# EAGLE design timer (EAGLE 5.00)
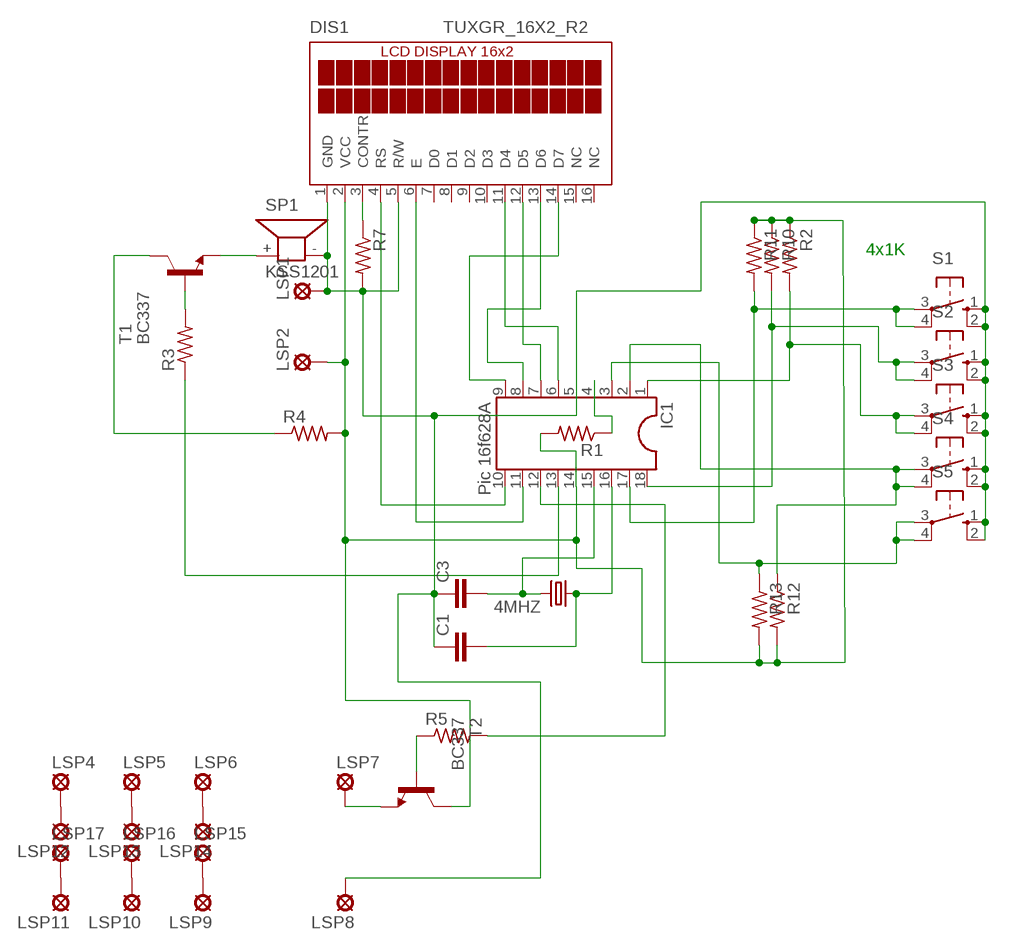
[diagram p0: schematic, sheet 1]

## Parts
4MHZ  CRYSTALHC18U-V  [HC18U-V]
C1  C2,5-3  [C2.5-3]
C3  C2,5-3  [C2.5-3]
DIS1  TUXGR_16X2_R2  [TUXGR_16X2_R2]
IC1  Pic 16f628A  DIL18  [DIL18]
LSP1  SE14  [SE14]
LSP2  SE14  [SE14]
LSP4  LSP10  [LSP10]
LSP5  LSP10  [LSP10]
LSP6  LSP10  [LSP10]
LSP7  LSP10  [LSP10]
LSP8  LSP10  [LSP10]
LSP9  LSP10  [LSP10]
LSP10  LSP10  [LSP10]
LSP11  LSP10  [LSP10]
LSP12  LSP10  [LSP10]
LSP13  LSP10  [LSP10]
LSP14  LSP10  [LSP10]
LSP15  LSP10  [LSP10]
LSP16  LSP10  [LSP10]
LSP17  LSP10  [LSP10]
R1  R-US_0204/7  [0204/7]
R2  R-US_0204/7  [0204/7]
R3  R-US_0204/7  [0204/7]
R4  R-US_0204/7  [0204/7]
R5  R-US_0204/7  [0204/7]
R7  R-US_0204/7  [0204/7]
R10  R-US_0204/7  [0204/7]
R11  R-US_0204/7  [0204/7]
R12  R-US_0204/7  [0204/7]
R13  R-US_0204/7  [0204/7]
S1  10-XX  [B3F-10XX]
S2  10-XX  [B3F-10XX]
S3  10-XX  [B3F-10XX]
S4  10-XX  [B3F-10XX]
S5  10-XX  [B3F-10XX]
SP1  KSS1201  [KSS1201]
T1  BC337  [TO92]
T2  BC337  [TO92]

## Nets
N$1: DIS1.3(CONTR) R7.1
N$2: 4MHZ.2 C3.2 IC1.15
N$3: DIS1.12(D5) IC1.7
N$4: IC1.12 R5.2
N$5: C1.1 C3.1 DIS1.1(GND) DIS1.5(R/W) IC1.5 LSP1.MP LSP8.MP R7.2 S1.1(S) S1.2(S1) S2.1(S) S2.2(S1) S3.1(S) S3.2(S1) S4.1(S) S4.2(S1) S5.1(S) S5.2(S1) SP1.-
N$6: IC1.4 R1.1
N$7: IC1.13 R3.1
N$8: DIS1.11(D4) IC1.6
N$9: DIS1.2(VCC) IC1.14 LSP2.MP R1.2 R2.1 R4.2 R10.1 R11.1 R12.2 R13.2 T2.3(C)
N$10: DIS1.4(RS) IC1.10
N$11: DIS1.6(E) IC1.11
N$12: DIS1.14(D7) IC1.9
N$13: SP1.+ T1.1(E)
N$14: IC1.3 R13.1 S5.3(P) S5.4(P1)
N$15: R4.1 T1.3(C)
N$16: IC1.17 R11.2 S1.3(P) S1.4(P1)
N$17: R3.2 T1.2(B)
N$18: 4MHZ.1 C1.2 IC1.16
N$19: LSP4.MP LSP12.MP
N$20: IC1.18 R10.2 S2.3(P) S2.4(P1)
N$21: IC1.1 R2.2 S3.3(P) S3.4(P1)
N$22: LSP5.MP LSP13.MP
N$23: LSP6.MP LSP14.MP
N$24: IC1.2 R12.1 S4.3(P) S4.4(P1)
N$25: LSP9.MP LSP15.MP
N$26: DIS1.13(D6) IC1.8
N$27: LSP10.MP LSP16.MP
N$28: LSP11.MP LSP17.MP
N$29: LSP7.MP T2.1(E)
N$31: R5.1 T2.2(B)
Unconnected: DIS1.7(D0) DIS1.8(D1) DIS1.9(D2) DIS1.10(D3) DIS1.15(NC) DIS1.16(NC)

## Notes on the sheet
- 4x1K

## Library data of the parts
4MHZ = crystal:CRYSTAL: CRYSTAL
C1 C3 = capacitor-wima:C: CAPACITOR
DIS1 = display-lcd:TUXGR_16X2_R2: Tuxgraphics LCD display 16x2 characters reflective, without background light Source: tuxgr_12x2_r2.pdf
IC1 = ic-package:DIL18: Dual In Line / Socket
LSP1 LSP2 = solpad:SE14: SOLDER PAD
LSP4-LSP17 = solpad:LSP10: SOLDER PAD
R1-R5 R7 R10-R13 = rcl:R-US_: RESISTOR, American symbol
S1-S5 = switch-omron:10-XX: OMRON SWITCH
SP1 = buzzer:KSS1201: SPEAKER
T1 T2 = transistor:BC337: NPN TRANSISTOR

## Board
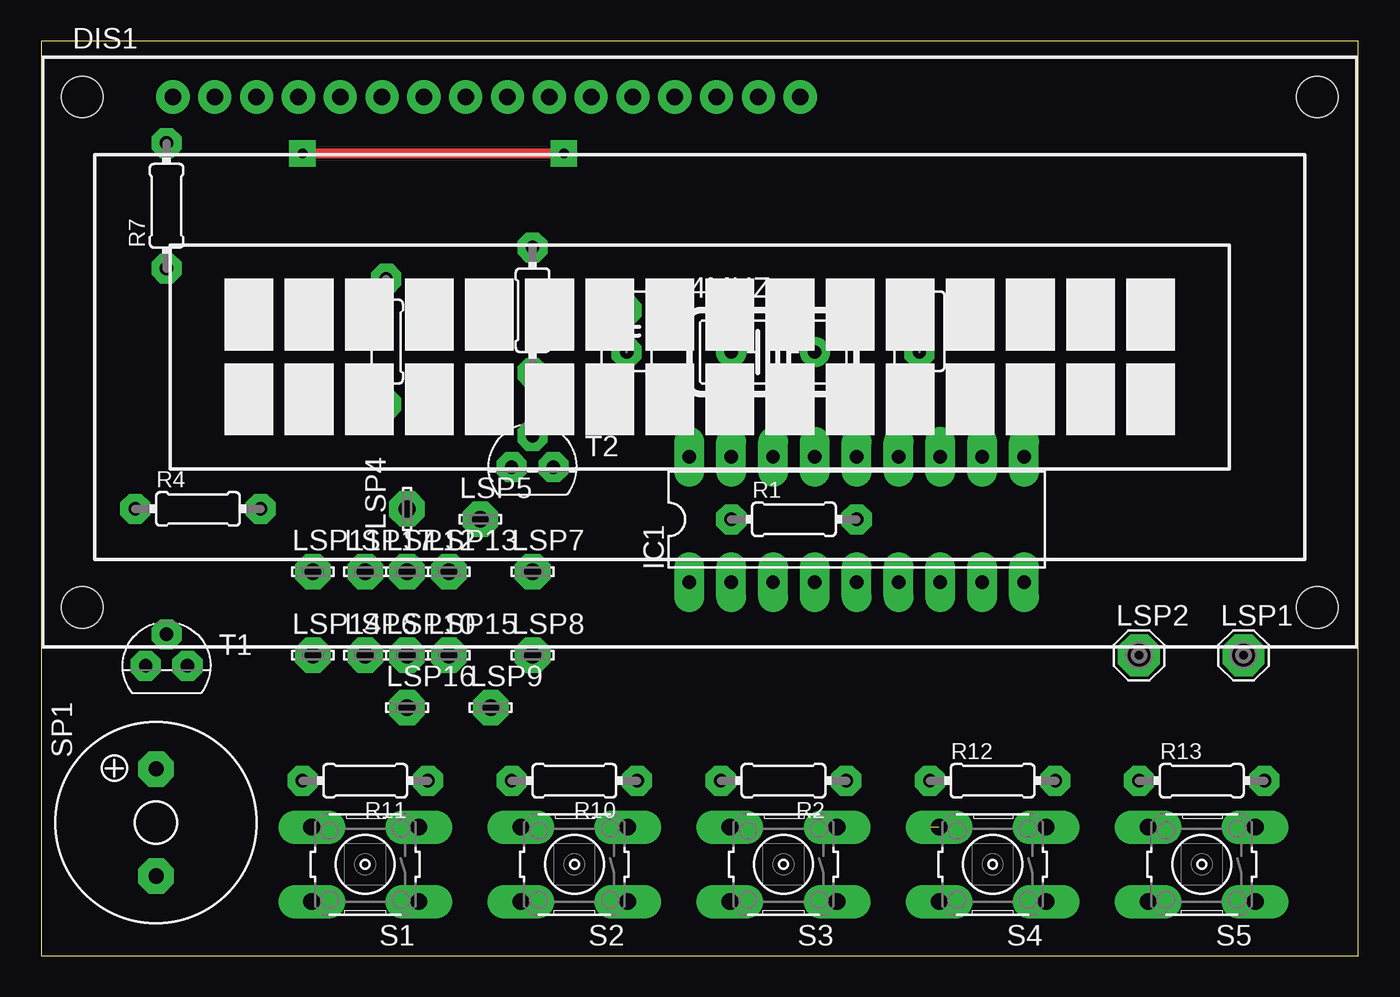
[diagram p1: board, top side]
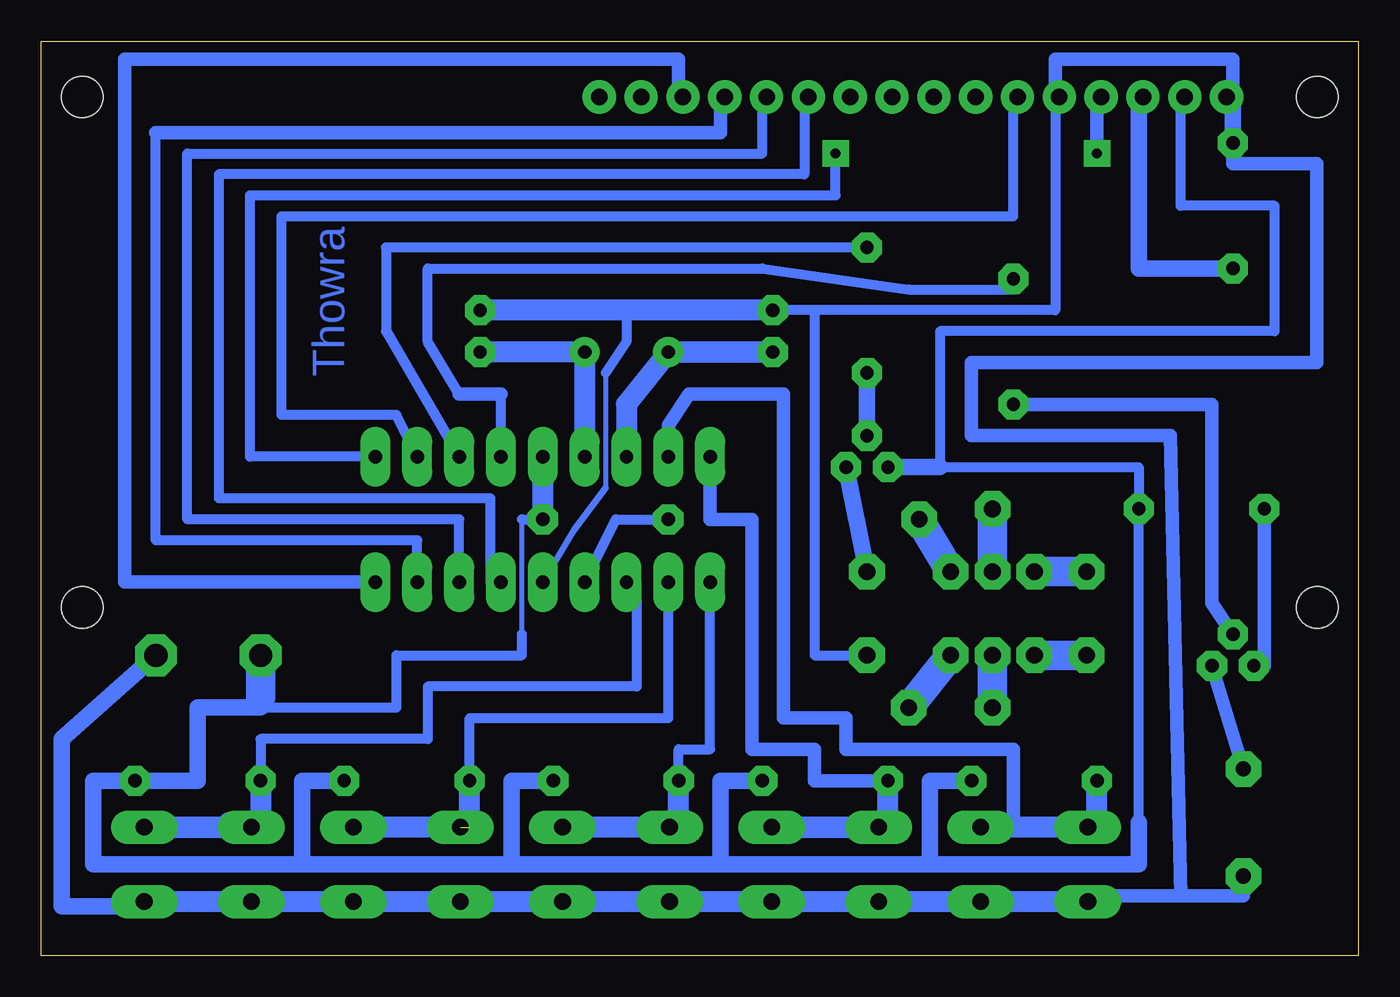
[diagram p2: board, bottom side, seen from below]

Size 79.99 x 55.55 mm. Coordinates in mm from the lower left corner, seen from the top.
Outline: 0,0 79.99,0 79.99,55.55 0,55.55 0,0
Copper layers (1*16): Top 0.035mm / dielectric 1.5mm / Bottom 0.035mm
Design rules "default *": minimum track width 10mil, minimum drill 0.0025mm, track to track 8mil, track to pad 8mil, pad to pad 8mil, via to via 8mil, smd to smd 8mil, copper to edge 40mil, drill to drill 8mil, minimum pad ring 20mil, minimum via ring 20mil, stop-mask expansion 4mil, vias tented up to drill 0mil, thermal gap 10mil

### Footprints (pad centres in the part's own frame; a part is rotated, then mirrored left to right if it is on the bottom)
HC18U-V = drill 0.813 round: 1 -2.54,0; 2 2.54,0
C2.5-3 = drill 0.813 pad 1.6 octagon: 1 -1.27,0; 2 1.27,0
TUXGR_16X2_R2 = drill 1 pad 1.676 round: 1 -32,15.5; 2 -29.46,15.5; 3 -26.92,15.5; 4 -24.38,15.5; 5 -21.84,15.5; 6 -19.3,15.5; 7 -16.76,15.5; 8 -14.22,15.5; 9 -11.68,15.5; 10 -9.14,15.5; 11 -6.6,15.5; 12 -4.06,15.5; 13 -1.52,15.5; 14 1.02,15.5; 15 3.56,15.5; 16 6.1,15.5 | hole 2.5: -37.5,-15.5; 37.5,-15.5; -37.5,15.5; 37.5,15.5
DIL18 = drill 0.813 long: 1 -10.16,-3.81; 2 -7.62,-3.81; 3 -5.08,-3.81; 4 -2.54,-3.81; 5 0,-3.81; 6 2.54,-3.81; 7 5.08,-3.81; 8 7.62,-3.81; 9 10.16,-3.81; 10 10.16,3.81; 11 7.62,3.81; 12 5.08,3.81; 13 2.54,3.81; 14 0,3.81; 15 -2.54,3.81; 16 -5.08,3.81; 17 -7.62,3.81; 18 -10.16,3.81
SE14 = drill 1.397 pad 2.54 octagon: MP 0,0
LSP10 = drill 1.016 pad 2.159 octagon: MP 0,0
0204/7 = drill 0.813 octagon: 1 -3.81,0; 2 3.81,0
B3F-10XX = drill 1.016 long: 1 -3.251,2.261; 2 3.251,2.261; 3 -3.251,-2.261; 4 3.251,-2.261
KSS1201 = drill 0.914 pad 2.159 octagon: + 3.251,0; - -3.251,0
TO92 = drill 0.813 octagon: 1 1.27,0; 2 0,1.905; 3 -1.27,0

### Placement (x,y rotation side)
4MHZ  44.45,36.66 0 top
C1  35.55,37.94 270 top
C3  53.34,37.94 270 top
DIS1  40,36.66 0 top
IC1  49.52,26.51 0 top
LSP1  73.02,18.25 0 top
LSP2  66.67,18.25 0 top
LSP4  22.22,27.14 90 top
LSP5  26.66,26.51 0 top
LSP6  19.68,18.25 0 top
LSP7  29.84,23.33 0 top
LSP8  29.84,18.25 0 top
LSP9  27.3,15.08 0 top
LSP10  22.22,18.25 0 top
LSP11  16.5,23.33 0 top
LSP12  22.22,23.33 0 top
LSP13  24.76,23.33 0 top
LSP14  16.5,18.25 0 top
LSP15  24.76,18.25 0 top
LSP16  22.22,15.08 0 top
LSP17  19.68,23.33 0 top
R1  45.71,26.51 0 top
R2  45.08,10.63 180 top
R3  20.95,37.3 270 top
R4  9.52,27.14 0 top
R5  29.84,39.21 90 top
R7  7.62,45.55 90 top
R10  32.38,10.63 180 top
R11  19.68,10.63 180 top
R12  57.78,10.63 0 top
R13  70.48,10.63 0 top
S1  19.68,5.55 180 top
S2  32.38,5.55 180 top
S3  45.08,5.55 180 top
S4  57.78,5.55 180 top
S5  70.48,5.55 180 top
SP1  6.98,8.09 90 top
T1  7.62,17.62 0 top
T2  29.84,29.68 0 top

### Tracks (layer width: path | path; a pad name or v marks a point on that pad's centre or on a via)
N$1
  Bottom 1.016: DIS1.3 13.33,52.16 13.33,41.74 R7.1
N$2
  Bottom 1.27: C3.2 4MHZ.2 IC1.15
N$3
  Bottom 0.61: IC1.7 54.6,26.51 71.12,26.51 71.12,48.73 36.19,48.73 36.19,52.16 DIS1.12
N$4
  Bottom 0.61: R5.2 59.05,43.02 59.05,37.94 IC1.12
N$5
  Bottom 0.305: 45.71,35.4 45.71,28.41
  Bottom 0.406: IC1.5 47.62,25.87 45.71,28.41
  Bottom 0.61: 45.71,35.4 44.45,37.3 44.45,39.21 | 33.02,39.21 18.41,39.21 18.41,52.16 | 33.02,39.21 C1.1 | 7.62,54.45 7.62,52.16 | SP1.- 6.98,4.92 | LSP8.MP 33.02,18.25 33.02,39.21
  Bottom 0.813: 18.41,52.16 18.41,54.45 7.62,54.45 7.62,48.1 2.54,48.1 2.54,36.03 23.49,36.03 23.49,31.59 11.43,31.59 10.79,3.65 | 10.79,3.65 16.5,3.65 | 10.79,3.65 6.98,3.65 SP1.-
  Bottom 1.016: 67.31,3.29 67.31,3.65 | 18.41,52.16 DIS1.5 | DIS1.1 7.62,52.16 R7.2 | LSP1.MP 78.73,13.17 78.73,3.01 73.66,3.01 73.66,3.29 S5.1
  Bottom 1.27: S4.1 S5.2 67.31,3.29 | S4.2 S4.1 | S3.1 S4.2 | S2.1 S3.2 | S2.2 S2.1 | S1.1 S2.2 | 22.22,3.29 S1.2 16.5,3.29 16.5,3.65 | 22.22,3.29 S1.1 | 22.22,3.29 22.22,3.65 | S1.1 S2.2 | S2.2 29.2,3.29 29.2,3.01 | S2.1 35.55,3.29 | S2.2 35.55,3.29 | 35.55,3.29 35.55,3.01 | S2.1 S3.2 | S3.2 41.91,3.29 41.91,3.01 | 48.25,3.29 S3.1 | S3.2 48.25,3.29 | 48.25,3.29 48.25,3.01 | S3.1 S4.2 | S4.2 54.6,3.29 54.6,3.01 | S4.2 S4.1 | S4.1 61.59,3.29 61.59,3.01 60.95,3.01 60.95,3.29 S4.1 | 67.31,3.29 S5.1 | 67.31,3.29 67.31,3.01 | C1.1 44.45,39.21 C3.1
N$6
  Bottom 0.61: IC1.4 45.08,26.51 R1.1
N$7
  Bottom 0.61: 54.6,34.13 56.51,37.3 56.51,41.74 36.19,41.74 27.3,40.48 20.95,40.48 R3.1 | IC1.13 52.06,34.13
  Bottom 0.813: 52.06,34.13 54.6,34.13
N$8
  Bottom 0.61: IC1.6 52.7,22.7 52.7,27.77 69.21,27.77 69.21,47.46 33.65,47.46 33.65,52.16 DIS1.11
N$9
  Bottom 0.305: 50.8,19.52 50.8,26.51
  Bottom 0.61: 50.8,26.51 R1.2 | 50.8,19.52 50.8,18.25 58.41,18.25 58.41,15.08 66.67,15.08 | DIS1.2 10.79,52.16 10.79,45.55 5.07,45.55 5.07,37.94 25.39,37.94 25.39,29.68 13.33,29.68 R4.2 13.33,8.09
  Bottom 1.016: R11.1 26.03,10.63 26.03,5.55 | 26.03,5.55 38.73,5.55 | R10.1 38.73,10.63 38.73,5.55 | 38.73,5.55 51.43,5.55 | R2.1 51.43,10.63 51.43,5.55 | 51.43,5.55 64.13,5.55 | R12.2 64.13,10.63 64.13,5.55 | 64.13,5.55 76.83,5.55 76.83,10.63 R13.2 70.48,10.63 70.48,15.08 66.67,15.08 66.67,15.71 | 13.33,8.09 13.33,5.55 26.03,5.55 | 25.39,29.68 T2.3
  Bottom 1.27: R1.2 IC1.14
  Bottom 1.778: 66.67,15.71 LSP2.MP
N$10  (via drill 0.6)
  Top 0.61: v31.74,48.73 v15.87,48.73
  Bottom 0.61: IC1.10 67.31,30.32 67.31,46.19 31.74,46.19 v31.74,48.73
  Bottom 0.813: DIS1.4 15.87,52.16 v15.87,48.73
N$11
  Bottom 0.61: IC1.11 58.41,32.85 65.4,32.85 65.4,44.92 20.95,44.92 20.95,52.16 DIS1.6
N$12
  Bottom 0.61: DIS1.14 41.27,52.16
  Bottom 0.813: 41.27,52.16 41.27,54.45 74.93,54.45 74.93,22.7 IC1.9
N$13
  Bottom 0.61: 6.98,11.27 SP1.+
  Bottom 0.813: T1.1 SP1.+
N$14
  Bottom 0.61: IC1.3 43.81,22.7 43.81,16.35 56.51,16.35 56.51,13.17 66.67,13.17 R13.1
  Bottom 1.27: S5.4 68.58,7.81 | 68.58,7.81 S5.3 66.67,7.81 R13.1 | 68.58,7.81 68.58,8.09
N$15
  Bottom 0.813: T1.3 5.71,17.62 R4.1
N$16
  Bottom 0.813: IC1.17 41.91,32.22 40.63,34.13 34.92,34.13 34.92,14.44 31.11,14.44 31.11,12.54 20.95,12.54 20.95,7.81
  Bottom 1.27: R11.2 15.87,7.81 S1.4 20.95,7.81 22.22,7.81 | 22.22,7.81 S1.3 | 22.22,7.81 22.22,8.09
N$17
  Bottom 0.813: R3.2 8.88,33.49 8.88,21.43 T1.2
N$18
  Bottom 1.27: 4MHZ.1 C1.2 4MHZ.1 | 4MHZ.1 44.45,33.49 IC1.16
N$19
  Bottom 1.778: LSP4.MP LSP12.MP
N$20
  Bottom 0.813: R10.2 33.02,10.63 33.02,12.54 36.82,12.54 36.82,26.51 39.37,26.51 IC1.18
  Bottom 1.27: 35.55,7.81 S2.3 28.57,7.81 R10.2 | S2.4 35.55,7.81 | 35.55,7.81 35.55,8.09
N$21
  Bottom 0.61: R2.2 41.27,12.54 39.37,12.54 IC1.1
  Bottom 1.27: S3.3 S3.4 41.27,7.81 R2.2
N$22
  Bottom 1.778: LSP5.MP LSP13.MP
N$23
  Bottom 1.778: LSP14.MP LSP6.MP
N$24  (1 unrouted)
  Bottom 0.61: R12.1 53.97,14.44 41.91,14.44 IC1.2
  Bottom 1.27: S4.3 53.97,7.81 R12.1
N$25
  Bottom 1.778: LSP9.MP LSP15.MP
N$26
  Bottom 0.61: IC1.8 57.14,25.24 73.02,25.24 73.02,50 | 38.73,52.16 DIS1.13
  Bottom 0.813: 73.02,50 38.73,50 38.73,52.16
N$27
  Bottom 1.778: LSP16.MP LSP10.MP
N$28
  Bottom 1.778: LSP11.MP LSP17.MP
N$29
  Bottom 1.016: LSP7.MP T2.1
N$31
  Bottom 1.016: R5.1 T2.2
(copper drawn outside any net)
  shapes: Bottom area x1

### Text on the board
Bottom: Thowra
